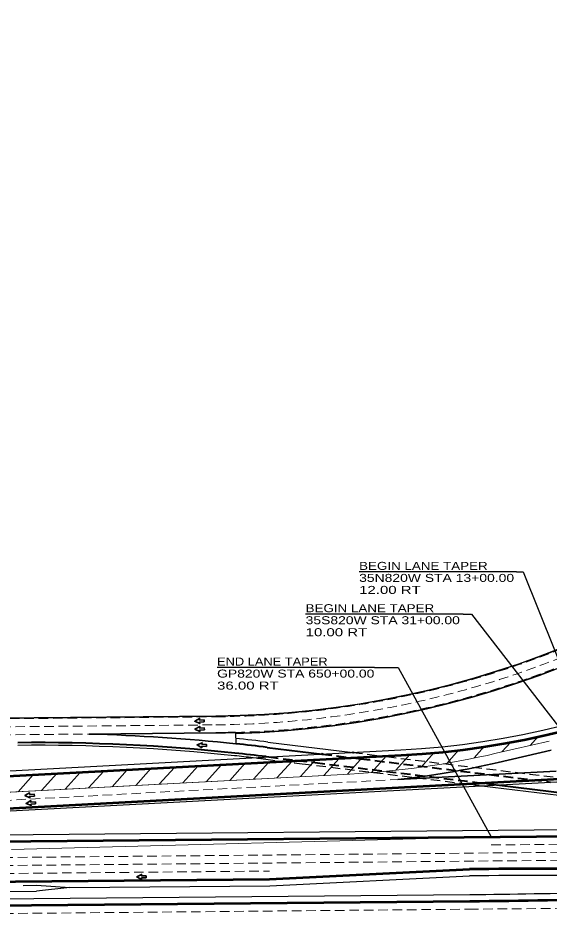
# Model space of a CAD drawing. Extents: x 2326434 to 2368642, y 6985225 to 6995090.
# Drawn here: x 2331414 to 2332211, y 6991238 to 6992583 of the extents above; entities that cross this region are included whole.
import ezdxf

# ---------------------------------------------------------------- set-up
doc = ezdxf.new("R2010")
doc.units = 0
doc.header["$LTSCALE"] = 4.8
doc.header["$PDMODE"] = 32
doc.header["$PDSIZE"] = 2.4
doc.linetypes.add('MEDIUM_DASHED', pattern=[4.5, 3, -1.5])
for name, color, linetype, lineweight in [('10', 7, 'Continuous', 35), ('26', 7, 'Continuous', 25), ('27', 7, 'Continuous', 25), ('28', 7, 'Continuous', 25), ('30', 7, 'Continuous', 25), ('40', 7, 'Continuous', 35), ('5', 7, 'Continuous', 25), ('50', 7, 'MEDIUM_DASHED', 13)]:
    doc.layers.add(name, color=color, linetype=linetype, lineweight=lineweight)

msp = doc.modelspace()

# ---------------------------------------------------------------- linework, layer by layer
at = {"layer": '10'}
for p, q in [((2331520.884, 6991509.376), (2331711.045, 6991511.153)), ((2332214.094, 6991485.234), (2332134.678, 6991466.83)), ((2331984.093, 6991441.237), (2332221.36, 6991453.88))]:
    msp.add_line(p, q, dxfattribs=at)
for centre, radius, start, end in [((2331921.237, 6992748.984), 1265.239, 273.05017, 273.05017), ((2331440.616, 6988645.712), 2864.789, 83.98494, 88.39441), ((2331697.424, 6992968.484), 1457.395, 270.53549, 271.68649), ((2331844.078, 6992720.839), 1287.239, 276.24449, 283.04721)]:
    msp.add_arc(centre, radius, start, end, dxfattribs=at)
at = {"layer": '26'}
for p, q in [((2330723.193, 6991352.028), (2332252.211, 6991366.314)), ((2330810.967, 6991256.844), (2332091.911, 6991268.812))]:
    msp.add_line(p, q, dxfattribs=at)
at = {"layer": '26', "lineweight": 53}
for p, q in [((2330723.287, 6991342.029), (2332252.305, 6991356.314)), ((2330686.071, 6991245.677), (2332092.005, 6991258.812))]:
    msp.add_line(p, q, dxfattribs=at)
at = {"layer": '27'}
for p, q in [((2331740.316, 6991511.721), (2331740.817, 6991494.728)), ((2331788.964, 6991497.303), (2331916.645, 6991481.705)), ((2331019.444, 6991433.897), (2331988.561, 6991485.537)), ((2330723.061, 6991358.019), (2332517.722, 6991453.649)), ((2332109.822, 6991431.914), (2332241.947, 6991415.773))]:
    msp.add_line(p, q, dxfattribs=at)
at = {"layer": '27', "lineweight": 40}
for p, q in [((2331787.994, 6991489.362), (2331870.708, 6991479.257)), ((2331786.297, 6991475.465), (2331790.318, 6991474.974)), ((2332132.79, 6991433.137), (2332242.432, 6991419.744))]:
    msp.add_line(p, q, dxfattribs=at)
at = {"layer": '27', "lineweight": 53}
for p, q in [((2331019.869, 6991425.908), (2331988.987, 6991477.549)), ((2330723.1, 6991362.027), (2332517.509, 6991457.643))]:
    msp.add_line(p, q, dxfattribs=at)
at = {"layer": '27', "linetype": 'MEDIUM_DASHED'}
for p, q in [((2331785.812, 6991471.494), (2331840.467, 6991464.818)), ((2331916.645, 6991481.705), (2331967.156, 6991475.535)), ((2331967.156, 6991475.535), (2332245.106, 6991441.581)), ((2331840.467, 6991464.818), (2332109.822, 6991431.914))]:
    msp.add_line(p, q, dxfattribs=at)
at = {"layer": '27', "linetype": 'MEDIUM_DASHED', "lineweight": 40}
for p, q in [((2331790.318, 6991474.974), (2331859.957, 6991466.467)), ((2331870.708, 6991479.257), (2331928.174, 6991472.237)), ((2331928.174, 6991472.237), (2332213.18, 6991437.421)), ((2331859.957, 6991466.467), (2332132.79, 6991433.137))]:
    msp.add_line(p, q, dxfattribs=at)
at = {"layer": '27'}
for centre, radius, start, end in [((2331921.237, 6992748.984), 1265.239, 273.05017, 359.32438), ((2331440.616, 6988645.712), 2872.789, 83.03529, 84.00651), ((2331440.616, 6988645.712), 2846.789, 83.98494, 90.53549), ((2331440.616, 6988645.712), 2846.789, 83.41682, 83.98494)]:
    msp.add_arc(centre, radius, start, end, dxfattribs=at)
at = {"layer": '27', "lineweight": 53}
msp.add_arc((2331921.237, 6992748.984), 1273.239, 273.05017, 359.32438, dxfattribs=at)
at = {"layer": '27', "lineweight": 40}
for radius, start, end in [(2850.789, 83.98494, 90.53549), (2864.789, 83.03529, 83.98494), (2850.789, 83.03529, 83.98494)]:
    msp.add_arc((2331440.616, 6988645.712), radius, start, end, dxfattribs=at)
at = {"layer": '27', "linetype": 'MEDIUM_DASHED'}
msp.add_arc((2331440.616, 6988645.712), 2846.789, 83.03529, 83.41682, dxfattribs=at)
at = {"layer": '27'}
for p in [(2331916.645, 6991481.705), (2331870.708, 6991479.257)]:
    msp.add_point(p, dxfattribs=at)
at = {"layer": '28'}
for p, q in [((2330905.067, 6991529.122), (2331710.807, 6991536.652)), ((2330905.072, 6991528.622), (2331710.811, 6991536.152)), ((2330810.865, 6991267.844), (2331441.837, 6991273.739)), ((2331491.788, 6991279.206), (2331441.837, 6991273.739))]:
    msp.add_line(p, q, dxfattribs=at)
at = {"layer": '28', "lineweight": 53}
msp.add_lwpolyline([(2330810.724, 6991282.843), (2331791.682, 6991292.008), (2332091.556, 6991306.81)], dxfattribs=at)
at = {"layer": '28'}
for points in [[(2331491.788, 6991279.206), (2331791.775, 6991282.008), (2332091.65, 6991296.811)], [(2331421.754, 6991282.552), (2331441.753, 6991282.738), (2331491.788, 6991279.206)]]:
    msp.add_lwpolyline(points, dxfattribs=at)
for radius, start in [(1431.895, 270.53549), (1432.395, 270.53549), (1458.395, 271.68649), (1458.895, 271.68649)]:
    msp.add_arc((2331697.424, 6992968.484), radius, start, 359.76624, dxfattribs=at)
at = {"layer": '30', "lineweight": 53}
for centre, start, end in [((2332198.613, 6979848.154), 88.20208, 90.53529), ((2331984.949, 7002717.468), 270.53529, 272.86849)]:
    msp.add_arc(centre, 11459.156, start, end, dxfattribs=at)
at = {"layer": '30'}
for centre, start, end in [((2332198.613, 6979848.154), 88.20208, 90.53529), ((2331984.949, 7002717.468), 270.53529, 272.46562)]:
    msp.add_arc(centre, 11449.156, start, end, dxfattribs=at)
at = {"layer": '40'}
for points in [[(2331693.431, 6991527.452), (2331693.332, 6991530.451), (2331686.529, 6991530.226), (2331686.448, 6991532.662), (2331679.377, 6991528.647), (2331686.698, 6991525.109), (2331686.628, 6991527.227)], [(2331693.715, 6991515.589), (2331693.616, 6991518.588), (2331686.813, 6991518.363), (2331686.732, 6991520.799), (2331679.661, 6991516.784), (2331686.982, 6991513.245), (2331686.912, 6991515.364)], [(2331696.749, 6991490.524), (2331696.946, 6991493.519), (2331690.154, 6991493.966), (2331690.314, 6991496.398), (2331682.881, 6991493.101), (2331689.817, 6991488.857), (2331689.957, 6991490.972)], [(2331438.666, 6991416.196), (2331438.491, 6991419.192), (2331431.696, 6991418.795), (2331431.554, 6991421.228), (2331424.586, 6991417.036), (2331431.994, 6991413.683), (2331431.871, 6991415.799)], [(2331440.385, 6991404.625), (2331440.21, 6991407.621), (2331433.415, 6991407.224), (2331433.273, 6991409.657), (2331426.305, 6991405.465), (2331433.714, 6991402.112), (2331433.59, 6991404.228)], [(2331606.419, 6991293.714), (2331606.37, 6991296.714), (2331599.564, 6991296.602), (2331599.524, 6991299.039), (2331592.387, 6991295.142), (2331599.648, 6991291.483), (2331599.613, 6991293.602)]]:
    msp.add_lwpolyline(points, close=True, dxfattribs=at)
at = {"layer": '5'}
for p, q in [((2332162.102, 6991752.381), (2331925.948, 6991752.381)), ((2332081.854, 6991688.943), (2331845.7, 6991688.943)), ((2331948.979, 6991608.974), (2331712.825, 6991608.974))]:
    msp.add_line(p, q, dxfattribs=at)
for points in [[(2332162.102, 6991752.381), (2332171.82, 6991752.241), (2332290.477, 6991457.563)], [(2332081.854, 6991688.943), (2332094.392, 6991688.943), (2332237.277, 6991505.271)], [(2331948.979, 6991608.974), (2331984.508, 6991608.964), (2332124.131, 6991355.117)]]:
    msp.add_lwpolyline(points, dxfattribs=at)
at = {"layer": '50'}
for p, q in [((2330870.195, 6991515.295), (2331710.933, 6991523.153)), ((2330905.081, 6991527.622), (2331710.821, 6991535.152)), ((2330870.307, 6991503.296), (2331520.884, 6991509.376)), ((2331023.378, 6991390.044), (2331984.093, 6991441.237)), ((2332124.243, 6991343.117), (2332252.417, 6991344.315)), ((2329664.221, 6991308.133), (2332252.529, 6991332.315)), ((2329664.333, 6991296.134), (2332252.641, 6991320.316)), ((2330810.612, 6991294.843), (2331791.57, 6991304.008))]:
    msp.add_line(p, q, dxfattribs=at)
at = {"layer": '50', "linetype": 'Continuous'}
for p, q in [((2332210.933, 6991498.872), (2332131.517, 6991480.469)), ((2332131.517, 6991480.469), (2332210.933, 6991498.872)), ((2332140.039, 6991482.444), (2332153.436, 6991497.349)), ((2332182.497, 6991492.283), (2332194.486, 6991505.622)), ((2332057.802, 6991465.746), (2332075.283, 6991485.195)), ((2332098.337, 6991473.446), (2332113.766, 6991490.612)), ((2331802.58, 6991443.582), (2331825.269, 6991468.825)), ((2331837.885, 6991445.463), (2331860.574, 6991470.706)), ((2331873.191, 6991447.344), (2331895.879, 6991472.587)), ((2331908.496, 6991449.225), (2331931.185, 6991474.469)), ((2331944.413, 6991451.788), (2331966.49, 6991476.35)), ((2331981.124, 6991455.233), (2332001.997, 6991478.455)), ((2332018.807, 6991459.76), (2332038.123, 6991481.25)), ((2331555.443, 6991430.413), (2331578.132, 6991455.656)), ((2331590.749, 6991432.294), (2331613.437, 6991457.537)), ((2331626.054, 6991434.175), (2331648.743, 6991459.418)), ((2331661.359, 6991436.057), (2331684.048, 6991461.3)), ((2331696.664, 6991437.938), (2331719.353, 6991463.181)), ((2331731.97, 6991439.819), (2331754.658, 6991465.062)), ((2331767.275, 6991441.7), (2331789.964, 6991466.943)), ((2331022.739, 6991402.027), (2331911.828, 6991449.403)), ((2331414.222, 6991422.888), (2331436.911, 6991448.131)), ((2331449.527, 6991424.769), (2331472.216, 6991450.012)), ((2331484.833, 6991426.65), (2331507.522, 6991451.893)), ((2331520.138, 6991428.532), (2331542.827, 6991453.775)), ((2331404.275, 6991336.391), (2332124.131, 6991355.117))]:
    msp.add_line(p, q, dxfattribs=at)
for points in [[(2331988.987, 6991477.549), (2331019.869, 6991425.908), (2330720.933, 6991397.962), (2330392.434, 6991380.458)], [(2330074.514, 6991341.486), (2330722.355, 6991376.007), (2331022.739, 6991402.027), (2331911.828, 6991449.403)]]:
    msp.add_lwpolyline(points, dxfattribs=at)
at = {"layer": '50'}
msp.add_lwpolyline([(2329665.005, 6991224.137), (2332090.455, 6991246.797), (2332253.314, 6991248.319)], dxfattribs=at)
for radius, start in [(1433.395, 270.53549), (1445.395, 270.53549), (1457.395, 271.68649)]:
    msp.add_arc((2331697.424, 6992968.484), radius, start, 359.76624, dxfattribs=at)
at = {"layer": '50', "linetype": 'Continuous'}
for centre, end in [((2331921.237, 6992748.984), 311.25764), ((2331844.078, 6992720.839), 283.04721), ((2331844.078, 6992720.839), 283.04721)]:
    msp.add_arc(centre, 1273.239, 273.05017, end, dxfattribs=at)

# ---------------------------------------------------------------- texts
at = {"layer": '5'}
for s, width, p in [('BEGIN LANE TAPER', 1.25, (2331925.947, 6991755.381)), ('35N820W STA 13+00.00', 1.3, (2331925.947, 6991737.381)), ('12.00 RT', 1.4, (2331925.948, 6991719.381)), ('BEGIN LANE TAPER', 1.25, (2331845.699, 6991691.943)), ('35S820W STA 31+00.00', 1.3, (2331845.699, 6991673.943)), ('10.00 RT', 1.4, (2331845.7, 6991655.943)), ('END LANE TAPER', 1.2, (2331712.824, 6991611.974)), ('GP820W STA 650+00.00', 1.3, (2331712.824, 6991593.974)), ('36.00 RT', 1.4, (2331712.825, 6991575.974))]:
    msp.add_text(s, height=12, dxfattribs=dict(at, width=width)).set_placement(p)

doc.saveas('drawing.dxf')
